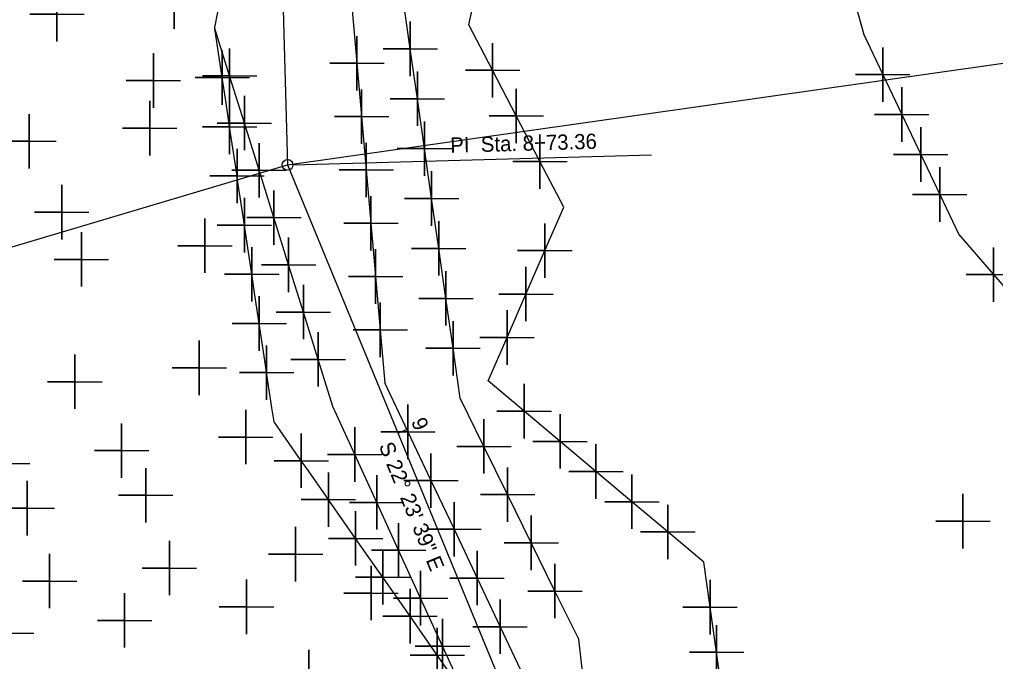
# Model space of a CAD drawing. Extents: x 2260968 to 2264340, y 653057 to 655850.
# Drawn here: x 2261691.8 to 2261781.6, y 654869.4 to 654928.3 of the extents above; entities that cross this region are included whole.
import ezdxf

# ---------------------------------------------------------------- set-up
doc = ezdxf.new("R2010")
doc.units = 0
for name, color, linetype in [('CL_X_Construction', 7, 'Continuous'), ('Default', 7, 'Continuous'), ('GE_X_CL_10', 7, 'Continuous'), ('GK_Patterns2', 7, 'Continuous')]:
    doc.layers.add(name, color=color, linetype=linetype)

msp = doc.modelspace()

# ---------------------------------------------------------------- linework, layer by layer
at = {"layer": 'CL_X_Construction'}
for p, q in [((2261714.109, 655001.598), (2261716.474, 654914.987)), ((2261714.109, 655001.598), (2261716.474, 654914.987)), ((2261716.474, 654914.987), (2261743.195, 654850.138)), ((2261716.474, 654914.987), (2261743.195, 654850.138))]:
    msp.add_line(p, q, dxfattribs=at)
at = {"layer": 'Default'}
for points in [[(2261706.06, 654930), (2261706.06, 654932.5), (2261706.06, 654930), (2261703.56, 654930), (2261706.06, 654930), (2261706.06, 654927.5), (2261706.06, 654930), (2261708.56, 654930)], [(2261756.498, 654866.057), (2261755.909, 654870.203), (2261755.32, 654874.348), (2261754.731, 654878.493), (2261751.43, 654881.266), (2261748.129, 654884.039), (2261744.828, 654886.812), (2261741.527, 654889.585), (2261738.226, 654892.358), (2261734.926, 654895.131), (2261736.658, 654899.124), (2261738.391, 654903.116), (2261740.124, 654907.108), (2261741.857, 654911.1), (2261739.679, 654915.292), (2261737.502, 654919.483), (2261735.325, 654923.675), (2261733.147, 654927.866), (2261734.186, 654932.659)], [(2261695.28, 654928.83), (2261695.28, 654931.33), (2261695.28, 654928.83), (2261692.78, 654928.83), (2261695.28, 654928.83), (2261695.28, 654926.33), (2261695.28, 654928.83), (2261697.78, 654928.83)], [(2261768.249, 654931.246), (2261769.442, 654926.96), (2261771.188, 654923.285), (2261772.935, 654919.611), (2261774.682, 654915.936), (2261776.428, 654912.261), (2261778.175, 654908.586), (2261781.358, 654904.909), (2261784.541, 654901.232)], [(2261732.733, 654866.378), (2261730.718, 654870.778), (2261728.703, 654875.177), (2261726.688, 654879.576), (2261724.673, 654883.975), (2261722.658, 654888.374), (2261720.643, 654892.773), (2261719.287, 654897.117), (2261717.93, 654901.46), (2261716.573, 654905.803), (2261715.216, 654910.147), (2261713.859, 654914.49), (2261712.502, 654918.833), (2261711.145, 654923.177), (2261709.788, 654927.52), (2261709.802, 654927.594), (2261710.333, 654930.466)], [(2261743.815, 654866.539), (2261743.236, 654871.399), (2261741.058, 654875.83), (2261738.879, 654880.261), (2261736.701, 654884.691), (2261734.522, 654889.122), (2261732.344, 654893.553), (2261731.688, 654898.138), (2261731.031, 654902.724), (2261730.375, 654907.309), (2261729.718, 654911.894), (2261729.062, 654916.48), (2261728.405, 654921.065), (2261727.749, 654925.651), (2261727.092, 654930.236)], [(2261722.424, 654929.212), (2261722.853, 654924.316), (2261723.282, 654919.419), (2261723.711, 654914.522), (2261724.14, 654909.626), (2261724.569, 654904.729), (2261724.998, 654899.833), (2261725.427, 654894.936), (2261727.544, 654890.459), (2261729.66, 654885.982), (2261731.776, 654881.506), (2261733.892, 654877.029), (2261736.009, 654872.552), (2261738.125, 654868.075)], [(2261732.733, 654866.378), (2261730.233, 654869.95), (2261727.732, 654873.522), (2261725.776, 654876.317), (2261725.232, 654877.093), (2261724.687, 654877.873), (2261722.732, 654880.665), (2261720.339, 654884.083), (2261720.232, 654884.237), (2261718.177, 654887.172), (2261717.732, 654887.808), (2261715.231, 654891.38), (2261715.039, 654892.658), (2261714.551, 654895.898), (2261714.385, 654896.998), (2261713.871, 654900.415), (2261713.447, 654903.231), (2261713.19, 654904.933), (2261712.731, 654907.981), (2261712.51, 654909.45), (2261711.916, 654913.391), (2261711.83, 654913.968), (2261711.149, 654918.485), (2261711.047, 654919.164), (2261710.792, 654920.857), (2261710.469, 654923.003), (2261710.406, 654923.422), (2261709.788, 654927.52)], [(2261727.749, 654925.651), (2261727.749, 654928.151), (2261727.749, 654925.651), (2261725.249, 654925.651), (2261727.749, 654925.651), (2261727.749, 654923.151), (2261727.749, 654925.651), (2261730.249, 654925.651)], [(2261722.853, 654924.316), (2261722.853, 654926.816), (2261722.853, 654924.316), (2261720.353, 654924.316), (2261722.853, 654924.316), (2261722.853, 654921.816), (2261722.853, 654924.316), (2261725.353, 654924.316)], [(2261735.325, 654923.675), (2261735.325, 654926.175), (2261735.325, 654923.675), (2261732.825, 654923.675), (2261735.325, 654923.675), (2261735.325, 654921.175), (2261735.325, 654923.675), (2261737.825, 654923.675)], [(2261771.188, 654923.285), (2261771.188, 654925.785), (2261771.188, 654923.285), (2261768.688, 654923.285), (2261771.188, 654923.285), (2261771.188, 654920.785), (2261771.188, 654923.285), (2261773.688, 654923.285)], [(2261704.14, 654922.74), (2261704.14, 654925.24), (2261704.14, 654922.74), (2261701.64, 654922.74), (2261704.14, 654922.74), (2261704.14, 654920.24), (2261704.14, 654922.74), (2261706.64, 654922.74)], [(2261710.469, 654923.003), (2261710.469, 654925.503), (2261710.469, 654923.003), (2261707.969, 654923.003), (2261710.469, 654923.003), (2261710.469, 654920.503), (2261710.469, 654923.003), (2261712.969, 654923.003)], [(2261711.145, 654923.177), (2261711.145, 654925.677), (2261711.145, 654923.177), (2261708.645, 654923.177), (2261711.145, 654923.177), (2261711.145, 654920.677), (2261711.145, 654923.177), (2261713.645, 654923.177)], [(2261728.405, 654921.065), (2261728.405, 654923.565), (2261728.405, 654921.065), (2261725.905, 654921.065), (2261728.405, 654921.065), (2261728.405, 654918.565), (2261728.405, 654921.065), (2261730.905, 654921.065)], [(2261712.502, 654918.833), (2261712.502, 654921.333), (2261712.502, 654918.833), (2261710.002, 654918.833), (2261712.502, 654918.833), (2261712.502, 654916.333), (2261712.502, 654918.833), (2261715.002, 654918.833)], [(2261723.282, 654919.419), (2261723.282, 654921.919), (2261723.282, 654919.419), (2261720.782, 654919.419), (2261723.282, 654919.419), (2261723.282, 654916.919), (2261723.282, 654919.419), (2261725.782, 654919.419)], [(2261737.502, 654919.483), (2261737.502, 654921.983), (2261737.502, 654919.483), (2261735.002, 654919.483), (2261737.502, 654919.483), (2261737.502, 654916.983), (2261737.502, 654919.483), (2261740.002, 654919.483)], [(2261772.935, 654919.611), (2261772.935, 654922.111), (2261772.935, 654919.611), (2261770.435, 654919.611), (2261772.935, 654919.611), (2261772.935, 654917.111), (2261772.935, 654919.611), (2261775.435, 654919.611)], [(2261703.8, 654918.36), (2261703.8, 654920.86), (2261703.8, 654918.36), (2261701.3, 654918.36), (2261703.8, 654918.36), (2261703.8, 654915.86), (2261703.8, 654918.36), (2261706.3, 654918.36)], [(2261711.149, 654918.485), (2261711.149, 654920.985), (2261711.149, 654918.485), (2261708.649, 654918.485), (2261711.149, 654918.485), (2261711.149, 654915.985), (2261711.149, 654918.485), (2261713.649, 654918.485)], [(2261692.71, 654917.15), (2261692.71, 654919.65), (2261692.71, 654917.15), (2261690.21, 654917.15), (2261692.71, 654917.15), (2261692.71, 654914.65), (2261692.71, 654917.15), (2261695.21, 654917.15)], [(2261729.062, 654916.48), (2261729.062, 654918.98), (2261729.062, 654916.48), (2261726.562, 654916.48), (2261729.062, 654916.48), (2261729.062, 654913.98), (2261729.062, 654916.48), (2261731.562, 654916.48)], [(2261739.679, 654915.292), (2261739.679, 654917.792), (2261739.679, 654915.292), (2261737.179, 654915.292), (2261739.679, 654915.292), (2261739.679, 654912.792), (2261739.679, 654915.292), (2261742.179, 654915.292)], [(2261774.682, 654915.936), (2261774.682, 654918.436), (2261774.682, 654915.936), (2261772.182, 654915.936), (2261774.682, 654915.936), (2261774.682, 654913.436), (2261774.682, 654915.936), (2261777.182, 654915.936)], [(2261713.859, 654914.49), (2261713.859, 654916.99), (2261713.859, 654914.49), (2261711.359, 654914.49), (2261713.859, 654914.49), (2261713.859, 654911.99), (2261713.859, 654914.49), (2261716.359, 654914.49)], [(2261723.711, 654914.522), (2261723.711, 654917.022), (2261723.711, 654914.522), (2261721.211, 654914.522), (2261723.711, 654914.522), (2261723.711, 654912.022), (2261723.711, 654914.522), (2261726.211, 654914.522)], [(2261711.83, 654913.968), (2261711.83, 654916.468), (2261711.83, 654913.968), (2261709.33, 654913.968), (2261711.83, 654913.968), (2261711.83, 654911.468), (2261711.83, 654913.968), (2261714.33, 654913.968)], [(2261729.718, 654911.894), (2261729.718, 654914.394), (2261729.718, 654911.894), (2261727.218, 654911.894), (2261729.718, 654911.894), (2261729.718, 654909.394), (2261729.718, 654911.894), (2261732.218, 654911.894)], [(2261776.428, 654912.261), (2261776.428, 654914.761), (2261776.428, 654912.261), (2261773.928, 654912.261), (2261776.428, 654912.261), (2261776.428, 654909.761), (2261776.428, 654912.261), (2261778.928, 654912.261)], [(2261695.72, 654910.64), (2261695.72, 654913.14), (2261695.72, 654910.64), (2261693.22, 654910.64), (2261695.72, 654910.64), (2261695.72, 654908.14), (2261695.72, 654910.64), (2261698.22, 654910.64)], [(2261715.216, 654910.147), (2261715.216, 654912.647), (2261715.216, 654910.147), (2261712.716, 654910.147), (2261715.216, 654910.147), (2261715.216, 654907.647), (2261715.216, 654910.147), (2261717.716, 654910.147)], [(2261712.51, 654909.45), (2261712.51, 654911.95), (2261712.51, 654909.45), (2261710.01, 654909.45), (2261712.51, 654909.45), (2261712.51, 654906.95), (2261712.51, 654909.45), (2261715.01, 654909.45)], [(2261724.14, 654909.626), (2261724.14, 654912.126), (2261724.14, 654909.626), (2261721.64, 654909.626), (2261724.14, 654909.626), (2261724.14, 654907.126), (2261724.14, 654909.626), (2261726.64, 654909.626)], [(2261708.88, 654907.56), (2261708.88, 654910.06), (2261708.88, 654907.56), (2261706.38, 654907.56), (2261708.88, 654907.56), (2261708.88, 654905.06), (2261708.88, 654907.56), (2261711.38, 654907.56)], [(2261730.375, 654907.309), (2261730.375, 654909.809), (2261730.375, 654907.309), (2261727.875, 654907.309), (2261730.375, 654907.309), (2261730.375, 654904.809), (2261730.375, 654907.309), (2261732.875, 654907.309)], [(2261740.124, 654907.108), (2261740.124, 654909.608), (2261740.124, 654907.108), (2261737.624, 654907.108), (2261740.124, 654907.108), (2261740.124, 654904.608), (2261740.124, 654907.108), (2261742.624, 654907.108)], [(2261697.52, 654906.3), (2261697.52, 654908.8), (2261697.52, 654906.3), (2261695.02, 654906.3), (2261697.52, 654906.3), (2261697.52, 654903.8), (2261697.52, 654906.3), (2261700.02, 654906.3)], [(2261716.573, 654905.803), (2261716.573, 654908.303), (2261716.573, 654905.803), (2261714.073, 654905.803), (2261716.573, 654905.803), (2261716.573, 654903.303), (2261716.573, 654905.803), (2261719.073, 654905.803)], [(2261713.19, 654904.933), (2261713.19, 654907.433), (2261713.19, 654904.933), (2261710.69, 654904.933), (2261713.19, 654904.933), (2261713.19, 654902.433), (2261713.19, 654904.933), (2261715.69, 654904.933)], [(2261724.569, 654904.729), (2261724.569, 654907.229), (2261724.569, 654904.729), (2261722.069, 654904.729), (2261724.569, 654904.729), (2261724.569, 654902.229), (2261724.569, 654904.729), (2261727.069, 654904.729)], [(2261781.358, 654904.909), (2261781.358, 654907.409), (2261781.358, 654904.909), (2261778.858, 654904.909), (2261781.358, 654904.909), (2261781.358, 654902.409), (2261781.358, 654904.909), (2261783.858, 654904.909)], [(2261731.031, 654902.724), (2261731.031, 654905.224), (2261731.031, 654902.724), (2261728.531, 654902.724), (2261731.031, 654902.724), (2261731.031, 654900.224), (2261731.031, 654902.724), (2261733.531, 654902.724)], [(2261738.391, 654903.116), (2261738.391, 654905.616), (2261738.391, 654903.116), (2261735.891, 654903.116), (2261738.391, 654903.116), (2261738.391, 654900.616), (2261738.391, 654903.116), (2261740.891, 654903.116)], [(2261717.93, 654901.46), (2261717.93, 654903.96), (2261717.93, 654901.46), (2261715.43, 654901.46), (2261717.93, 654901.46), (2261717.93, 654898.96), (2261717.93, 654901.46), (2261720.43, 654901.46)], [(2261713.871, 654900.415), (2261713.871, 654902.915), (2261713.871, 654900.415), (2261711.371, 654900.415), (2261713.871, 654900.415), (2261713.871, 654897.915), (2261713.871, 654900.415), (2261716.371, 654900.415)], [(2261724.998, 654899.833), (2261724.998, 654902.333), (2261724.998, 654899.833), (2261722.498, 654899.833), (2261724.998, 654899.833), (2261724.998, 654897.333), (2261724.998, 654899.833), (2261727.498, 654899.833)], [(2261736.658, 654899.124), (2261736.658, 654901.624), (2261736.658, 654899.124), (2261734.158, 654899.124), (2261736.658, 654899.124), (2261736.658, 654896.624), (2261736.658, 654899.124), (2261739.158, 654899.124)], [(2261731.688, 654898.138), (2261731.688, 654900.638), (2261731.688, 654898.138), (2261729.188, 654898.138), (2261731.688, 654898.138), (2261731.688, 654895.638), (2261731.688, 654898.138), (2261734.188, 654898.138)], [(2261708.36, 654896.34), (2261708.36, 654898.84), (2261708.36, 654896.34), (2261705.86, 654896.34), (2261708.36, 654896.34), (2261708.36, 654893.84), (2261708.36, 654896.34), (2261710.86, 654896.34)], [(2261719.287, 654897.117), (2261719.287, 654899.617), (2261719.287, 654897.117), (2261716.787, 654897.117), (2261719.287, 654897.117), (2261719.287, 654894.617), (2261719.287, 654897.117), (2261721.787, 654897.117)], [(2261714.551, 654895.898), (2261714.551, 654898.398), (2261714.551, 654895.898), (2261712.051, 654895.898), (2261714.551, 654895.898), (2261714.551, 654893.398), (2261714.551, 654895.898), (2261717.051, 654895.898)], [(2261696.92, 654895.06), (2261696.92, 654897.56), (2261696.92, 654895.06), (2261694.42, 654895.06), (2261696.92, 654895.06), (2261696.92, 654892.56), (2261696.92, 654895.06), (2261699.42, 654895.06)], [(2261738.226, 654892.358), (2261738.226, 654894.858), (2261738.226, 654892.358), (2261735.726, 654892.358), (2261738.226, 654892.358), (2261738.226, 654889.858), (2261738.226, 654892.358), (2261740.726, 654892.358)], [(2261727.544, 654890.459), (2261727.544, 654892.959), (2261727.544, 654890.459), (2261725.044, 654890.459), (2261727.544, 654890.459), (2261727.544, 654887.959), (2261727.544, 654890.459), (2261730.044, 654890.459)], [(2261712.63, 654889.98), (2261712.63, 654892.48), (2261712.63, 654889.98), (2261710.13, 654889.98), (2261712.63, 654889.98), (2261712.63, 654887.48), (2261712.63, 654889.98), (2261715.13, 654889.98)], [(2261734.522, 654889.122), (2261734.522, 654891.622), (2261734.522, 654889.122), (2261732.022, 654889.122), (2261734.522, 654889.122), (2261734.522, 654886.622), (2261734.522, 654889.122), (2261737.022, 654889.122)], [(2261741.527, 654889.585), (2261741.527, 654892.085), (2261741.527, 654889.585), (2261739.027, 654889.585), (2261741.527, 654889.585), (2261741.527, 654887.085), (2261741.527, 654889.585), (2261744.027, 654889.585)], [(2261701.22, 654888.73), (2261701.22, 654891.23), (2261701.22, 654888.73), (2261698.72, 654888.73), (2261701.22, 654888.73), (2261701.22, 654886.23), (2261701.22, 654888.73), (2261703.72, 654888.73)], [(2261722.658, 654888.374), (2261722.658, 654890.874), (2261722.658, 654888.374), (2261720.158, 654888.374), (2261722.658, 654888.374), (2261722.658, 654885.874), (2261722.658, 654888.374), (2261725.158, 654888.374)], [(2261690.29, 654887.56), (2261690.29, 654890.06), (2261690.29, 654887.56), (2261687.79, 654887.56), (2261690.29, 654887.56), (2261690.29, 654885.06), (2261690.29, 654887.56), (2261692.79, 654887.56)], [(2261717.732, 654887.808), (2261717.732, 654890.308), (2261717.732, 654887.808), (2261715.232, 654887.808), (2261717.732, 654887.808), (2261717.732, 654885.308), (2261717.732, 654887.808), (2261720.232, 654887.808)], [(2261744.828, 654886.812), (2261744.828, 654889.312), (2261744.828, 654886.812), (2261742.328, 654886.812), (2261744.828, 654886.812), (2261744.828, 654884.312), (2261744.828, 654886.812), (2261747.328, 654886.812)], [(2261729.66, 654885.982), (2261729.66, 654888.482), (2261729.66, 654885.982), (2261727.16, 654885.982), (2261729.66, 654885.982), (2261729.66, 654883.482), (2261729.66, 654885.982), (2261732.16, 654885.982)], [(2261703.44, 654884.63), (2261703.44, 654887.13), (2261703.44, 654884.63), (2261700.94, 654884.63), (2261703.44, 654884.63), (2261703.44, 654882.13), (2261703.44, 654884.63), (2261705.94, 654884.63)], [(2261736.701, 654884.691), (2261736.701, 654887.191), (2261736.701, 654884.691), (2261734.201, 654884.691), (2261736.701, 654884.691), (2261736.701, 654882.191), (2261736.701, 654884.691), (2261739.201, 654884.691)], [(2261720.232, 654884.237), (2261720.232, 654886.737), (2261720.232, 654884.237), (2261717.732, 654884.237), (2261720.232, 654884.237), (2261720.232, 654881.737), (2261720.232, 654884.237), (2261722.732, 654884.237)], [(2261724.673, 654883.975), (2261724.673, 654886.475), (2261724.673, 654883.975), (2261722.173, 654883.975), (2261724.673, 654883.975), (2261724.673, 654881.475), (2261724.673, 654883.975), (2261727.173, 654883.975)], [(2261748.129, 654884.039), (2261748.129, 654886.539), (2261748.129, 654884.039), (2261745.629, 654884.039), (2261748.129, 654884.039), (2261748.129, 654881.539), (2261748.129, 654884.039), (2261750.629, 654884.039)], [(2261692.55, 654883.45), (2261692.55, 654885.95), (2261692.55, 654883.45), (2261690.05, 654883.45), (2261692.55, 654883.45), (2261692.55, 654880.95), (2261692.55, 654883.45), (2261695.05, 654883.45)], [(2261778.56, 654882.249), (2261778.56, 654884.749), (2261778.56, 654882.249), (2261776.06, 654882.249), (2261778.56, 654882.249), (2261778.56, 654879.749), (2261778.56, 654882.249), (2261781.06, 654882.249)], [(2261731.776, 654881.506), (2261731.776, 654884.006), (2261731.776, 654881.506), (2261729.276, 654881.506), (2261731.776, 654881.506), (2261731.776, 654879.006), (2261731.776, 654881.506), (2261734.276, 654881.506)], [(2261751.43, 654881.266), (2261751.43, 654883.766), (2261751.43, 654881.266), (2261748.93, 654881.266), (2261751.43, 654881.266), (2261751.43, 654878.766), (2261751.43, 654881.266), (2261753.93, 654881.266)], [(2261722.732, 654880.665), (2261722.732, 654883.165), (2261722.732, 654880.665), (2261720.232, 654880.665), (2261722.732, 654880.665), (2261722.732, 654878.165), (2261722.732, 654880.665), (2261725.232, 654880.665)], [(2261738.879, 654880.261), (2261738.879, 654882.761), (2261738.879, 654880.261), (2261736.379, 654880.261), (2261738.879, 654880.261), (2261738.879, 654877.761), (2261738.879, 654880.261), (2261741.379, 654880.261)], [(2261726.688, 654879.576), (2261726.688, 654882.076), (2261726.688, 654879.576), (2261724.188, 654879.576), (2261726.688, 654879.576), (2261726.688, 654877.076), (2261726.688, 654879.576), (2261729.188, 654879.576)], [(2261717.21, 654879.22), (2261717.21, 654881.72), (2261717.21, 654879.22), (2261714.71, 654879.22), (2261717.21, 654879.22), (2261717.21, 654876.72), (2261717.21, 654879.22), (2261719.71, 654879.22)], [(2261705.61, 654877.94), (2261705.61, 654880.44), (2261705.61, 654877.94), (2261703.11, 654877.94), (2261705.61, 654877.94), (2261705.61, 654875.44), (2261705.61, 654877.94), (2261708.11, 654877.94)], [(2261694.6, 654876.75), (2261694.6, 654879.25), (2261694.6, 654876.75), (2261692.1, 654876.75), (2261694.6, 654876.75), (2261694.6, 654874.25), (2261694.6, 654876.75), (2261697.1, 654876.75)], [(2261725.232, 654877.093), (2261725.232, 654879.593), (2261725.232, 654877.093), (2261722.732, 654877.093), (2261725.232, 654877.093), (2261725.232, 654874.593), (2261725.232, 654877.093), (2261727.732, 654877.093)], [(2261733.892, 654877.029), (2261733.892, 654879.529), (2261733.892, 654877.029), (2261731.392, 654877.029), (2261733.892, 654877.029), (2261733.892, 654874.529), (2261733.892, 654877.029), (2261736.392, 654877.029)], [(2261741.058, 654875.83), (2261741.058, 654878.33), (2261741.058, 654875.83), (2261738.558, 654875.83), (2261741.058, 654875.83), (2261741.058, 654873.33), (2261741.058, 654875.83), (2261743.558, 654875.83)], [(2261724.15, 654875.65), (2261724.15, 654878.15), (2261724.15, 654875.65), (2261721.65, 654875.65), (2261724.15, 654875.65), (2261724.15, 654873.15), (2261724.15, 654875.65), (2261726.65, 654875.65)], [(2261728.703, 654875.177), (2261728.703, 654877.677), (2261728.703, 654875.177), (2261726.203, 654875.177), (2261728.703, 654875.177), (2261728.703, 654872.677), (2261728.703, 654875.177), (2261731.203, 654875.177)], [(2261712.7, 654874.38), (2261712.7, 654876.88), (2261712.7, 654874.38), (2261710.2, 654874.38), (2261712.7, 654874.38), (2261712.7, 654871.88), (2261712.7, 654874.38), (2261715.2, 654874.38)], [(2261755.32, 654874.348), (2261755.32, 654876.848), (2261755.32, 654874.348), (2261752.82, 654874.348), (2261755.32, 654874.348), (2261755.32, 654871.848), (2261755.32, 654874.348), (2261757.82, 654874.348)], [(2261701.49, 654873.14), (2261701.49, 654875.64), (2261701.49, 654873.14), (2261698.99, 654873.14), (2261701.49, 654873.14), (2261701.49, 654870.64), (2261701.49, 654873.14), (2261703.99, 654873.14)], [(2261727.732, 654873.522), (2261727.732, 654876.022), (2261727.732, 654873.522), (2261725.232, 654873.522), (2261727.732, 654873.522), (2261727.732, 654871.022), (2261727.732, 654873.522), (2261730.232, 654873.522)], [(2261736.009, 654872.552), (2261736.009, 654875.052), (2261736.009, 654872.552), (2261733.509, 654872.552), (2261736.009, 654872.552), (2261736.009, 654870.052), (2261736.009, 654872.552), (2261738.509, 654872.552)], [(2261690.65, 654871.96), (2261690.65, 654874.46), (2261690.65, 654871.96), (2261688.15, 654871.96), (2261690.65, 654871.96), (2261690.65, 654869.46), (2261690.65, 654871.96), (2261693.15, 654871.96)], [(2261730.718, 654870.778), (2261730.718, 654873.278), (2261730.718, 654870.778), (2261728.218, 654870.778), (2261730.718, 654870.778), (2261730.718, 654868.278), (2261730.718, 654870.778), (2261733.218, 654870.778)], [(2261730.233, 654869.95), (2261730.233, 654872.45), (2261730.233, 654869.95), (2261727.733, 654869.95), (2261730.233, 654869.95), (2261730.233, 654867.45), (2261730.233, 654869.95), (2261732.733, 654869.95)], [(2261755.909, 654870.203), (2261755.909, 654872.703), (2261755.909, 654870.203), (2261753.409, 654870.203), (2261755.909, 654870.203), (2261755.909, 654867.703), (2261755.909, 654870.203), (2261758.409, 654870.203)], [(2261718.42, 654867.92), (2261718.42, 654870.42), (2261718.42, 654867.92), (2261715.92, 654867.92), (2261718.42, 654867.92), (2261718.42, 654865.42), (2261718.42, 654867.92), (2261720.92, 654867.92)]]:
    msp.add_lwpolyline(points, dxfattribs=at)
at = {"layer": 'GE_X_CL_10'}
for p, q in [((2261714.109, 655001.598), (2261716.474, 654914.987)), ((2261716.974, 654915), (2261749.917, 654915.9)), ((2261716.974, 654915), (2261749.917, 654915.9)), ((2261716.474, 654914.987), (2261743.195, 654850.138)), ((2261726.625, 654890.352), (2261727.549, 654890.733)), ((2261726.625, 654890.352), (2261727.549, 654890.733))]:
    msp.add_line(p, q, dxfattribs=at)
msp.add_circle((2261716.474, 654914.987), 0.5, dxfattribs=at)
msp.add_circle((2261716.474, 654914.987), 0.5, dxfattribs=at)
at = {"layer": 'GK_Patterns2'}
msp.add_lwpolyline([(2261625.894, 654888.04), (2261716.474, 654914.987), (2261966.488, 654950.52)], dxfattribs=at)

# ---------------------------------------------------------------- texts
at = {"layer": 'GE_X_CL_10'}
for s, rotation, p in [('PI  Sta. 8+73.36', 1.56415, (2261731.449, 654916.096)), ('PI  Sta. 8+73.36', 1.56415, (2261731.449, 654916.096)), ('9', 292.39418, (2261727.81, 654891.412)), ('9', 292.39418, (2261727.81, 654891.412)), ('S 22%%d 23\' 39" E', 292.39418, (2261724.838, 654889.176))]:
    msp.add_text(s, height=1.4, rotation=rotation, dxfattribs=at).set_placement(p)

doc.saveas('drawing.dxf')
